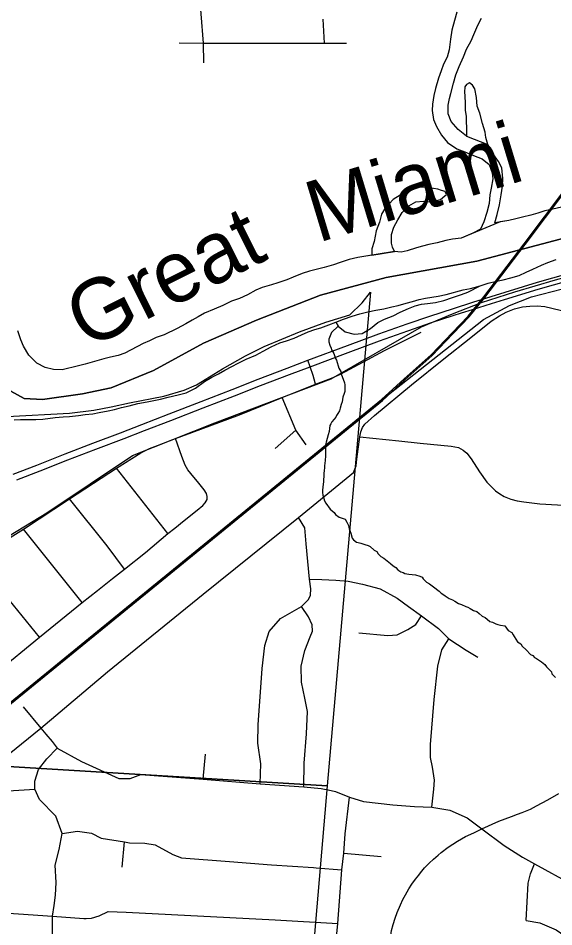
# Model space of a CAD drawing. Extents: x -7.3 to 34, y 0 to 22.
# Drawn here: x 2.852 to 3.68, y 15.96 to 17.363 of the extents above; entities that cross this region are included whole.
import ezdxf

# ---------------------------------------------------------------- set-up
doc = ezdxf.new("R2010")
doc.units = 0
for name, color, linetype in [('GM_X_City_Street', 7, 'Continuous'), ('GM_X_Corporation', 7, 'Continuous'), ('GM_X_County_Road', 7, 'Continuous'), ('GM_X_Major_River', 7, 'Continuous'), ('GM_X_Major_River_Text', 7, 'Continuous'), ('GM_X_Minor_River', 7, 'Continuous'), ('GM_X_Rail_Line', 7, 'Continuous'), ('GM_X_State_Route', 7, 'Continuous'), ('GM_X_Township_Road', 7, 'Continuous')]:
    doc.layers.add(name, color=color, linetype=linetype)

msp = doc.modelspace()

# ---------------------------------------------------------------- linework, layer by layer
at = {"layer": 'GM_X_City_Street'}
for p, q in [((3.2495, 16.6986), (3.2815, 16.7273)), ((3.084, 16.5678), (3.0044, 16.6683)), ((2.9513, 16.461), (2.8605, 16.5745)), ((3.1384, 16.1882), (3.1421, 16.227)), ((2.7616, 16.1658), (2.8784, 16.1728)), ((3.0134, 16.0522), (3.0169, 16.0912)), ((3.3559, 16.0738), (3.4137, 16.069)), ((3.313, 16.0513), (3.3525, 16.0483))]:
    msp.add_line(p, q, dxfattribs=at)
for points in [[(3.3806, 16.7168), (3.3818, 16.7247), (3.3844, 16.7311), (3.3881, 16.7366), (3.4032, 16.75), (3.4602, 16.7972), (3.5101, 16.8371), (3.5518, 16.8703), (3.5837, 16.8955), (3.5961, 16.9039), (3.6068, 16.9095), (3.6197, 16.9146), (3.6318, 16.9174), (3.643, 16.9187), (3.6546, 16.9189), (3.6665, 16.9179), (3.69, 16.9124), (3.7103, 16.9072), (3.7215, 16.9044), (3.7303, 16.9036), (3.7395, 16.9039), (3.7514, 16.904)], [(3.3121, 16.7984), (3.3369, 16.8077), (3.3504, 16.8138), (3.3864, 16.8327), (3.4188, 16.8503), (3.4752, 16.8784)], [(3.2976, 16.7043), (3.2815, 16.7273), (3.2607, 16.7777)], [(3.1447, 16.6201), (3.1446, 16.6246), (3.1434, 16.6296), (3.14, 16.6349), (3.1319, 16.6453), (3.1193, 16.6602), (3.1148, 16.6658), (3.1107, 16.6732), (3.1052, 16.6865), (3.0956, 16.7142)], [(3.3706, 16.6616), (3.3747, 16.6719), (3.3761, 16.6826), (3.3806, 16.7168)], [(2.451, 15.9102), (2.5692, 16.0102), (2.617, 16.0491), (2.6686, 16.0914), (2.7616, 16.1658), (2.8874, 16.2669), (2.9907, 16.354), (3.1385, 16.4741), (3.2859, 16.5922), (3.3706, 16.6616)], [(2.4737, 16.082), (2.5003, 16.0943), (2.5508, 16.1345), (2.6783, 16.2396), (2.685, 16.2457), (2.7515, 16.2992), (2.8184, 16.353), (2.8852, 16.4076), (2.9513, 16.461), (2.975, 16.4798), (2.9982, 16.4983), (3.0166, 16.5127), (3.0495, 16.5384), (3.084, 16.5678), (3.0945, 16.5756), (3.1088, 16.5876), (3.1289, 16.6036), (3.138, 16.611), (3.1414, 16.6147), (3.1447, 16.6201)], [(3.0166, 16.5127), (2.9898, 16.5486), (2.9319, 16.6213)], [(3.2267, 16.181), (3.2273, 16.2118), (3.2231, 16.2439), (3.2235, 16.272), (3.2297, 16.359), (3.2337, 16.3945), (3.2404, 16.4162), (3.2577, 16.4362), (3.2901, 16.4548), (3.3013, 16.4656), (3.3044, 16.4722), (3.3049, 16.4822), (3.3026, 16.4971), (3.2975, 16.5517), (3.2953, 16.5765), (3.2859, 16.5922)], [(2.8852, 16.4076), (2.8182, 16.4898), (2.8093, 16.5025), (2.801, 16.5158), (2.7927, 16.5321)], [(3.3026, 16.4971), (3.322, 16.4965), (3.3433, 16.4953), (3.3624, 16.494), (3.3847, 16.4894), (3.412, 16.4819), (3.4384, 16.4679), (3.4558, 16.4551), (3.4758, 16.4404), (3.5021, 16.4207), (3.5178, 16.405), (3.545, 16.3876), (3.5628, 16.3767)], [(3.2939, 16.1763), (3.2945, 16.2129), (3.2981, 16.2583), (3.2996, 16.2925), (3.2953, 16.3135), (3.2903, 16.3382), (3.2898, 16.3625), (3.2953, 16.3867), (3.3037, 16.4079), (3.3071, 16.4168), (3.3069, 16.4265), (3.3012, 16.4389), (3.2901, 16.4548)], [(3.379, 16.4141), (3.424, 16.41), (3.4381, 16.4113), (3.4548, 16.4192), (3.467, 16.4272), (3.4758, 16.4404)], [(3.4918, 16.145), (3.4947, 16.1728), (3.4961, 16.1866), (3.4929, 16.2065), (3.4897, 16.2217), (3.4895, 16.2415), (3.4956, 16.3112), (3.5008, 16.3629), (3.5072, 16.388), (3.5178, 16.405)], [(2.8601, 16.2999), (2.8874, 16.2669), (2.8954, 16.2578), (2.9049, 16.2462), (2.9129, 16.2363), (2.9503, 16.2156), (3.0083, 16.1891), (3.0256, 16.1891), (3.0421, 16.1952), (3.1384, 16.1882), (3.2267, 16.181), (3.2939, 16.1763), (3.3209, 16.1739), (3.3258, 16.1729)], [(2.8852, 15.856), (2.8914, 15.8756), (2.9053, 15.9451), (2.9054, 15.9766), (2.908, 15.9932), (2.91, 16.0092), (2.9111, 16.0286), (2.9096, 16.0553), (2.9158, 16.0798), (2.9204, 16.1043), (2.9105, 16.1312), (2.8852, 16.157), (2.8784, 16.1728), (2.878, 16.1851), (2.8839, 16.2031), (2.8969, 16.2196), (2.9129, 16.2363)], [(3.3258, 16.1729), (3.3317, 16.1717), (3.3428, 16.1694), (3.3647, 16.1606), (3.386, 16.1536), (3.4317, 16.1484), (3.4649, 16.146), (3.4918, 16.145), (3.5197, 16.1405), (3.5462, 16.1287), (3.5691, 16.1116), (3.6036, 16.086), (3.632, 16.0675), (3.6506, 16.0574), (3.7088, 16.0253), (3.7341, 16.0168), (3.7648, 16.013), (3.7864, 16.0151), (3.8265, 16.018), (3.8756, 16.0249), (3.9397, 16.0179), (3.9801, 16.0031), (3.9807, 16.0028), (4.0236, 15.9862)], [(3.3285, 15.7545), (3.3385, 15.882), (3.3464, 15.9652), (3.3525, 16.0483), (3.3559, 16.0738), (3.358, 16.1037), (3.3647, 16.1606)], [(2.9204, 16.1043), (2.9441, 16.1081), (2.9656, 16.1046), (2.9809, 16.0971), (3.0169, 16.0912), (3.0245, 16.0901), (3.0481, 16.0892), (3.0644, 16.0866), (3.0916, 16.0717), (3.105, 16.0665), (3.1793, 16.0611), (3.2438, 16.0559), (3.309, 16.0516), (3.313, 16.0513)], [(3.6375, 15.97), (3.6405, 16.0276), (3.6445, 16.0422), (3.6506, 16.0574)], [(2.5692, 16.0102), (2.5823, 16.0058), (2.6248, 16.0016), (2.7998, 15.9837), (2.9054, 15.9766), (2.9537, 15.9728), (2.9577, 15.973)], [(2.9577, 15.973), (2.9656, 15.9734), (2.9777, 15.977), (2.9914, 15.9837), (3.0195, 15.9828), (3.2499, 15.9709), (3.3464, 15.9652)], [(3.6375, 15.97), (3.6585, 15.9666), (3.684, 15.9555), (3.6971, 15.9464), (3.7075, 15.9375), (3.731, 15.9214), (3.7512, 15.9094), (3.7588, 15.9067), (3.8115, 15.8965), (3.8522, 15.8895), (3.8783, 15.8839), (3.9009, 15.8712), (3.9216, 15.8562), (3.9406, 15.8468), (3.9784, 15.8335), (4.0152, 15.8291), (4.0396, 15.8287), (4.0767, 15.8393), (4.1145, 15.8459), (4.1191, 15.8467), (4.1778, 15.8643), (4.1983, 15.8701)]]:
    msp.add_lwpolyline(points, dxfattribs=at)
at = {"layer": 'GM_X_Corporation'}
for points in [[(3.7543, 17.039), (3.5614, 16.9883), (3.4213, 16.9628), (3.3195, 16.9357), (3.2207, 16.8971), (3.1387, 16.8614), (3.0618, 16.8191), (2.996, 16.7927), (2.9517, 16.7835), (2.8903, 16.7745), (2.8615, 16.7762), (2.8411, 16.7875), (2.825, 16.807), (2.8151, 16.8289), (2.8045, 16.8509), (2.7965, 16.8622), (2.7873, 16.8705), (2.7646, 16.894), (2.72, 16.9194), (2.7253, 17.2786), (2.7319, 17.6124)], [(2.7319, 17.6124), (2.7253, 17.2786), (2.72, 16.9194), (2.7646, 16.894), (2.7873, 16.8705), (2.7965, 16.8622), (2.8045, 16.8509), (2.8151, 16.8289), (2.825, 16.807), (2.8411, 16.7875), (2.8615, 16.7762), (2.8903, 16.7745), (2.9517, 16.7835), (2.996, 16.7927), (3.0618, 16.8191), (3.1387, 16.8614), (3.2207, 16.8971), (3.3195, 16.9357), (3.4213, 16.9628), (3.5614, 16.9883), (3.7543, 17.039)], [(2.7319, 17.6124), (2.7253, 17.2786), (2.72, 16.9194), (2.7646, 16.894), (2.7873, 16.8705), (2.7965, 16.8622), (2.8045, 16.8509), (2.8151, 16.8289), (2.825, 16.807), (2.8411, 16.7875), (2.8615, 16.7762), (2.8903, 16.7745), (2.9517, 16.7835), (2.996, 16.7927), (3.0618, 16.8191), (3.1387, 16.8614), (3.2207, 16.8971), (3.3195, 16.9357), (3.4213, 16.9628), (3.5614, 16.9883), (3.7543, 17.039)], [(3.7543, 17.039), (3.5614, 16.9883), (3.4213, 16.9628), (3.3195, 16.9357), (3.2207, 16.8971), (3.1387, 16.8614), (3.0618, 16.8191), (2.996, 16.7927), (2.9517, 16.7835), (2.8903, 16.7745), (2.8615, 16.7762), (2.8411, 16.7875)], [(3.7543, 17.039), (3.5614, 16.9883), (3.4213, 16.9628), (3.3195, 16.9357), (3.2207, 16.8971), (3.1387, 16.8614), (3.0618, 16.8191), (2.996, 16.7927), (2.9517, 16.7835), (2.8903, 16.7745), (2.8615, 16.7762), (2.8411, 16.7875)], [(2.8353, 16.7484), (2.9316, 16.7533), (2.9692, 16.7582), (2.9962, 16.7633), (3.0243, 16.7692), (3.0776, 16.7799), (3.1092, 16.7887), (3.1279, 16.7971), (3.1682, 16.822), (3.2038, 16.8421), (3.2325, 16.8563), (3.2871, 16.8791), (3.3279, 16.8938), (3.3653, 16.9055), (3.3842, 16.9237), (3.397, 16.9401), (3.3302, 16.1779), (2.2589, 16.243)]]:
    msp.add_lwpolyline(points, dxfattribs=at)
msp.add_lwpolyline([(2.2589, 16.243), (3.3302, 16.1779), (3.2417, 15.1468), (2.2068, 15.2308)], close=True, dxfattribs=at)
at = {"layer": 'GM_X_County_Road'}
for points in [[(3.3806, 16.7168), (3.4407, 16.7108), (3.4738, 16.707), (3.5216, 16.7026), (3.5331, 16.7003), (3.5404, 16.6965), (3.5459, 16.6914), (3.5525, 16.6829), (3.5656, 16.6629), (3.577, 16.647), (3.5833, 16.6399), (3.5901, 16.6335), (3.5968, 16.6289), (3.6038, 16.6248), (3.614, 16.6206), (3.6237, 16.6179), (3.6342, 16.6163), (3.6585, 16.6136), (3.6858, 16.6117), (3.717, 16.6104), (3.773, 16.6064)], [(3.6241, 16.1339), (3.6314, 16.1366), (3.6445, 16.1421), (3.6537, 16.1471), (3.6713, 16.1565), (3.6882, 16.1659)], [(3.5691, 16.1116), (3.5952, 16.1231), (3.6151, 16.1304), (3.6241, 16.1339)], [(3.5014, 16.071), (3.5061, 16.0751), (3.5168, 16.083), (3.5317, 16.0923), (3.5438, 16.0996), (3.5565, 16.1053), (3.5691, 16.1116)], [(3.4262, 15.9355), (3.4269, 15.9402), (3.4282, 15.9472), (3.4297, 15.9546), (3.4319, 15.9636), (3.435, 15.9734), (3.4382, 15.9823), (3.4432, 15.994), (3.4471, 16.0023), (3.451, 16.0094), (3.4564, 16.0186), (3.4611, 16.026), (3.4664, 16.0336), (3.4715, 16.0401), (3.4743, 16.0437), (3.4807, 16.0511), (3.4877, 16.0586), (3.4943, 16.0648), (3.5014, 16.071)]]:
    msp.add_lwpolyline(points, dxfattribs=at)
at = {"layer": 'GM_X_Major_River'}
for p, q in [((3.5451, 17.181), (3.5785, 17.1681)), ((3.399, 16.9972), (3.434, 17.0028))]:
    msp.add_line(p, q, dxfattribs=at)
for points in [[(3.5304, 17.3725), (3.5267, 17.3597), (3.5229, 17.3446), (3.5206, 17.3309), (3.5187, 17.3147), (3.5153, 17.303), (3.5097, 17.2921), (3.5061, 17.2819), (3.5023, 17.2706), (3.4974, 17.2548), (3.4949, 17.2439)], [(3.5211, 17.2468), (3.5253, 17.2632), (3.529, 17.2757), (3.5339, 17.2888), (3.5407, 17.3035), (3.5456, 17.3155), (3.5524, 17.3286), (3.5568, 17.3384), (3.5629, 17.3527), (3.5685, 17.3636)], [(3.5785, 17.1681), (3.575, 17.1792), (3.5741, 17.1872), (3.5699, 17.2009), (3.5658, 17.2166), (3.5619, 17.2273), (3.5607, 17.2411), (3.5584, 17.254), (3.5544, 17.2598), (3.5499, 17.2634), (3.5453, 17.2608), (3.5429, 17.2571), (3.5424, 17.2491), (3.543, 17.2434), (3.5434, 17.2316), (3.5431, 17.2206), (3.5448, 17.2122), (3.545, 17.205), (3.5455, 17.1932), (3.5451, 17.181)], [(3.5451, 17.181), (3.5325, 17.1916), (3.5218, 17.2037), (3.5172, 17.2156), (3.5172, 17.2288), (3.5193, 17.2391), (3.5211, 17.2468)], [(3.4949, 17.2439), (3.493, 17.2306), (3.4923, 17.2207), (3.4946, 17.207), (3.4989, 17.1963), (3.5065, 17.1828), (3.5161, 17.1715), (3.5306, 17.1617), (3.5426, 17.1568), (3.5561, 17.1511), (3.5696, 17.1462), (3.5804, 17.1372), (3.585, 17.1246), (3.5859, 17.1151), (3.5836, 17.1007), (3.5815, 17.0905), (3.5803, 17.0772), (3.5766, 17.0633), (3.572, 17.049), (3.5668, 17.0377), (3.5552, 17.0313)], [(3.589, 17.0474), (3.5928, 17.0602), (3.5966, 17.0749), (3.5989, 17.0904), (3.6008, 17.1037), (3.6015, 17.1158), (3.6, 17.1322), (3.5949, 17.1418), (3.5847, 17.1565), (3.5785, 17.1681)], [(3.434, 17.0028), (3.4311, 17.0096), (3.4297, 17.0161), (3.4297, 17.0294), (3.433, 17.0407), (3.439, 17.0519), (3.4457, 17.0631), (3.4562, 17.0735), (3.467, 17.0797), (3.4788, 17.0809), (3.4924, 17.0798), (3.505, 17.0833), (3.512, 17.0892), (3.5147, 17.091), (3.5122, 17.0957), (3.5069, 17.0973), (3.5013, 17.0993), (3.4941, 17.1003), (3.4809, 17.1018), (3.4684, 17.1025), (3.455, 17.0975), (3.443, 17.0902), (3.4319, 17.0832), (3.426, 17.0765), (3.4202, 17.071), (3.4142, 17.0609), (3.4108, 17.0484), (3.4059, 17.0349), (3.4029, 17.0186), (3.3992, 17.0073), (3.399, 16.9972)], [(3.6924, 17.0716), (3.679, 17.0685), (3.6664, 17.0657), (3.6557, 17.0621), (3.645, 17.0593), (3.6317, 17.0561), (3.6214, 17.0537), (3.6107, 17.0509), (3.589, 17.0474)], [(3.6924, 17.0716), (3.679, 17.0685), (3.6664, 17.0657), (3.6557, 17.0621), (3.645, 17.0593), (3.6317, 17.0561), (3.6214, 17.0537), (3.6107, 17.0509), (3.5974, 17.0489)], [(3.5974, 17.0489), (3.5372, 17.0239), (3.5235, 17.0219), (3.5133, 17.0198), (3.4999, 17.0163), (3.4873, 17.0139), (3.4774, 17.0114), (3.4679, 17.0086), (3.4537, 17.0043), (3.4442, 17.0022), (3.434, 17.0028)], [(3.5552, 17.0313), (3.5372, 17.0239), (3.5235, 17.0219), (3.5133, 17.0198), (3.4999, 17.0163), (3.4873, 17.0139), (3.4774, 17.0114), (3.4679, 17.0086), (3.4537, 17.0043), (3.4442, 17.0022), (3.434, 17.0028)], [(3.434, 17.0028), (3.3776, 16.9937), (3.3642, 16.9906), (3.3501, 16.9863), (3.3398, 16.9824)], [(3.399, 16.9972), (3.3776, 16.9937), (3.3642, 16.9906), (3.3501, 16.9863), (3.3398, 16.9824)], [(2.8462, 16.743), (2.856, 16.7435), (2.8663, 16.7437), (2.8799, 16.7434), (2.8906, 16.744), (2.9096, 16.7466), (2.9222, 16.7475), (2.932, 16.7484), (2.9457, 16.7497), (2.956, 16.7514), (2.9678, 16.7526), (2.9777, 16.7543), (2.9914, 16.7571), (3.0013, 16.7592), (3.0124, 16.762), (3.0239, 16.7648), (3.0376, 16.7683), (3.0517, 16.771), (3.0723, 16.7752), (3.0845, 16.778), (3.0997, 16.7818), (3.1119, 16.7846), (3.1265, 16.7919), (3.1404, 16.8023), (3.1516, 16.8089), (3.1619, 16.8143), (3.1719, 16.8198), (3.1827, 16.8253), (3.1923, 16.8308), (3.2049, 16.837), (3.2199, 16.8432), (3.231, 16.849), (3.2437, 16.8556), (3.2567, 16.8621), (3.2674, 16.865), (3.2792, 16.8693), (3.2904, 16.8744), (3.3007, 16.8791), (3.3107, 16.8827), (3.3202, 16.8852), (3.3328, 16.8898), (3.3435, 16.8938), (3.3554, 16.8985), (3.3688, 16.9031), (3.3806, 16.9067), (3.3928, 16.9099), (3.405, 16.9123), (3.4176, 16.9143), (3.4298, 16.9175), (3.4397, 16.9199), (3.4519, 16.9235), (3.4619, 16.9259), (3.4722, 16.9288), (3.4821, 16.9308), (3.4916, 16.9325), (3.5015, 16.9339), (3.5141, 16.9366), (3.54, 16.9437), (3.5515, 16.9461), (3.5664, 16.95), (3.579, 16.9539), (3.5919, 16.9571), (3.6022, 16.9595), (3.6137, 16.9623), (3.6267, 16.9662), (3.6378, 16.9709), (3.6477, 16.9757), (3.6612, 16.9819), (3.6711, 16.9862), (3.6841, 16.9909)], [(3.3398, 16.9824), (3.3256, 16.9781), (3.3131, 16.9753), (3.3028, 16.9729), (3.2913, 16.9693), (3.2775, 16.9635), (3.2676, 16.9595), (3.2538, 16.9549), (3.2439, 16.9517), (3.2297, 16.9474), (3.2198, 16.9434), (3.2067, 16.9361), (3.1945, 16.9306), (3.1822, 16.9263), (3.1688, 16.9198), (3.1554, 16.914), (3.1404, 16.9078), (3.1308, 16.9023), (3.1212, 16.8972), (3.1116, 16.8913), (3.0982, 16.884), (3.0782, 16.8745), (3.0656, 16.8702), (3.0553, 16.8651), (3.0457, 16.8608), (3.0173, 16.8462), (3.007, 16.8426), (2.9951, 16.8398), (2.9848, 16.8373), (2.9703, 16.8331), (2.9562, 16.8292), (2.9455, 16.8264), (2.9203, 16.8201), (2.9071, 16.8207), (2.8942, 16.824), (2.8811, 16.8307), (2.8688, 16.8428), (2.8608, 16.857), (2.8565, 16.8669), (2.8522, 16.8803)], [(3.3398, 16.9824), (3.3256, 16.9781), (3.3131, 16.9753), (3.3028, 16.9729), (3.2913, 16.9693), (3.2775, 16.9635), (3.2676, 16.9595), (3.2538, 16.9549), (3.2439, 16.9517), (3.2297, 16.9474), (3.2198, 16.9434), (3.2067, 16.9361), (3.1945, 16.9306), (3.1822, 16.9263), (3.1688, 16.9198), (3.1554, 16.914), (3.1404, 16.9078), (3.1308, 16.9023), (3.1212, 16.8972), (3.1116, 16.8913), (3.0982, 16.884), (3.0782, 16.8745), (3.0656, 16.8702), (3.0553, 16.8651), (3.0457, 16.8608), (3.0173, 16.8462), (3.007, 16.8426), (2.9951, 16.8398), (2.9848, 16.8373), (2.9703, 16.8331), (2.9562, 16.8292), (2.9455, 16.8264), (2.9203, 16.8201), (2.9071, 16.8207), (2.8942, 16.824), (2.8811, 16.8307), (2.8688, 16.8428), (2.8608, 16.857), (2.8565, 16.8669), (2.8522, 16.8803)]]:
    msp.add_lwpolyline(points, dxfattribs=at)
at = {"layer": 'GM_X_Minor_River'}
for points in [[(3.3435, 16.8938), (3.3468, 16.888), (3.3576, 16.8791), (3.3716, 16.8754), (3.3841, 16.8762), (3.3968, 16.8843), (3.4084, 16.8932), (3.4188, 16.8987), (3.4318, 16.9038), (3.4429, 16.9092), (3.4556, 16.915), (3.4659, 16.9194), (3.4758, 16.9215), (3.4853, 16.9228), (3.4975, 16.9244), (3.5105, 16.9272), (3.5235, 16.9319), (3.5376, 16.9365), (3.5476, 16.9405), (3.5664, 16.95)], [(3.3468, 16.888), (3.3369, 16.8779), (3.3346, 16.8726), (3.3327, 16.8677), (3.3327, 16.8636), (3.3341, 16.8586), (3.3364, 16.8537), (3.3367, 16.851), (3.339, 16.8483), (3.3401, 16.8453), (3.3412, 16.8426), (3.3431, 16.8377), (3.3442, 16.835), (3.3479, 16.8228), (3.3509, 16.8175), (3.3516, 16.8141), (3.3568, 16.8004), (3.3571, 16.797), (3.3575, 16.7928), (3.3571, 16.7867), (3.3563, 16.7837), (3.3544, 16.778), (3.3532, 16.7708), (3.3516, 16.767), (3.3501, 16.761), (3.3489, 16.7568), (3.3466, 16.7527), (3.3447, 16.7497), (3.3432, 16.747), (3.3409, 16.744), (3.3374, 16.7399), (3.3355, 16.7368), (3.334, 16.7342), (3.3332, 16.7251), (3.3316, 16.7198), (3.3285, 16.7085), (3.3273, 16.7047), (3.3272, 16.688), (3.3268, 16.68), (3.3264, 16.6766), (3.326, 16.6717), (3.3259, 16.6683), (3.3255, 16.6656), (3.3251, 16.6596), (3.3247, 16.6558), (3.3243, 16.6512), (3.3243, 16.6478), (3.3231, 16.6391), (3.3227, 16.6345), (3.3226, 16.6311), (3.3234, 16.6266), (3.3241, 16.6239), (3.326, 16.6178), (3.3282, 16.6144), (3.3346, 16.6049), (3.3406, 16.5999), (3.3428, 16.5968), (3.3485, 16.593), (3.3519, 16.5918), (3.3579, 16.5895), (3.3605, 16.5853), (3.3631, 16.5799), (3.3638, 16.575), (3.3668, 16.5681), (3.3686, 16.5605), (3.3709, 16.5579), (3.3754, 16.5544), (3.378, 16.5536), (3.3818, 16.5525), (3.3882, 16.5505), (3.3935, 16.5489), (3.3965, 16.5474), (3.4029, 16.542), (3.4067, 16.5397), (3.4089, 16.5363), (3.4131, 16.5321), (3.4176, 16.5294), (3.4251, 16.5232), (3.4277, 16.5213), (3.4319, 16.5175), (3.436, 16.5152), (3.4394, 16.5117), (3.4439, 16.5086), (3.4477, 16.5075), (3.4503, 16.5059), (3.4563, 16.5047), (3.4666, 16.5035), (3.473, 16.5019), (3.4767, 16.5004), (3.4786, 16.4977), (3.4835, 16.4924), (3.4884, 16.49), (3.4944, 16.485), (3.503, 16.4785), (3.5061, 16.4755), (3.5087, 16.4739), (3.5124, 16.4712), (3.5188, 16.467), (3.5237, 16.4651), (3.5275, 16.4631), (3.5328, 16.4597)], [(3.5328, 16.4597), (3.5377, 16.4581), (3.5445, 16.4546), (3.5475, 16.4538), (3.5509, 16.4515), (3.5562, 16.4488), (3.5614, 16.4469), (3.5648, 16.4438), (3.5697, 16.44), (3.5742, 16.438), (3.5772, 16.4354), (3.5814, 16.4315), (3.5855, 16.4304), (3.5908, 16.428), (3.5938, 16.4269), (3.598, 16.4261), (3.6044, 16.4249), (3.6074, 16.4214), (3.61, 16.418), (3.6153, 16.4145), (3.6175, 16.4111), (3.619, 16.4084), (3.6242, 16.4004), (3.6291, 16.397), (3.6314, 16.3935), (3.6374, 16.3878), (3.6445, 16.3805), (3.6479, 16.379), (3.6505, 16.3763), (3.6536, 16.3744), (3.6611, 16.3694), (3.6637, 16.3671), (3.6663, 16.3651), (3.669, 16.3617), (3.6716, 16.359), (3.6765, 16.3537), (3.6772, 16.351), (3.6828, 16.3453)]]:
    msp.add_lwpolyline(points, dxfattribs=at)
at = {"layer": 'GM_X_Rail_Line'}
for points in [[(3.6345, 17.0151), (3.985, 17.4802), (4.3732, 17.9988), (4.5251, 18.2021), (4.7981, 18.5667), (5.0774, 18.9371), (5.1565, 19.0428), (5.1846, 19.0805), (5.2002, 19.101), (5.5499, 19.5711), (5.7863, 19.8846), (5.8776, 20.0139)], [(3.636, 17.0139), (3.9865, 17.479), (4.3757, 17.998), (4.5264, 18.1998), (4.796, 18.5597), (5.0789, 18.9359), (5.158, 19.0417), (5.1862, 19.0793), (5.2017, 19.0998), (5.5529, 19.5699), (5.7879, 19.8835), (5.8792, 20.0128)], [(3.5684, 16.9242), (3.6203, 16.9407), (3.683, 16.9592), (3.9788, 17.0405), (4.0548, 17.0607), (4.1528, 17.0906), (4.2816, 17.1367), (4.4251, 17.1935), (4.4536, 17.2072)], [(3.415, 16.7747), (3.5714, 16.898), (3.6117, 16.9195), (3.6457, 16.9333), (3.7099, 16.9497), (3.823, 16.9805), (3.8987, 17.0026), (4.0866, 17.0531), (4.2789, 17.1213), (4.4523, 17.1912)], [(2.1, 15.707), (2.1249, 15.7268), (2.5382, 16.0605), (2.9557, 16.4006), (3.414, 16.7747), (3.4488, 16.8065), (3.4909, 16.8436), (3.5233, 16.8776), (3.548, 16.9034), (3.5722, 16.9333), (3.6345, 17.0151)], [(2.1, 15.7046), (2.1261, 15.7254), (2.5394, 16.059), (2.9569, 16.3991), (3.4153, 16.7732), (3.4501, 16.805), (3.4922, 16.8422), (3.5247, 16.8762), (3.5495, 16.9022), (3.5737, 16.9321), (3.636, 17.0139)], [(2.1, 15.9624), (2.1372, 15.9999), (2.2187, 16.0756), (2.3348, 16.1655), (2.4005, 16.2159), (2.4362, 16.2448), (2.4901, 16.3128), (2.5242, 16.3462), (2.5948, 16.4062), (2.7068, 16.4842), (2.8968, 16.5994), (3.0293, 16.6878), (3.1562, 16.7383), (3.3361, 16.8064), (3.4758, 16.8869), (3.5239, 16.9069), (3.5684, 16.9242)]]:
    msp.add_lwpolyline(points, dxfattribs=at)
at = {"layer": 'GM_X_State_Route'}
for points in [[(2.8449, 16.6594), (2.8811, 16.6733), (2.9252, 16.6906), (2.9681, 16.7069), (3.0106, 16.7232), (3.0434, 16.7358), (3.0856, 16.7524), (3.1355, 16.7715), (3.1832, 16.7902), (3.2235, 16.8057), (3.2683, 16.8231), (3.3002, 16.835), (3.3616, 16.8579), (3.4101, 16.876), (3.4538, 16.8914), (3.4888, 16.9031), (3.5253, 16.915), (3.5549, 16.9246), (3.5833, 16.9337), (3.6553, 16.9555), (3.7025, 16.969)], [(3.6041, 16.929), (3.6562, 16.9447), (3.7034, 16.9583), (3.7179, 16.9623)], [(3.5375, 16.9083), (3.5547, 16.9137), (3.5842, 16.923), (3.6041, 16.929)], [(2.8502, 16.6506), (2.8863, 16.6645), (2.9293, 16.6811), (2.9726, 16.6978), (3.0161, 16.7145), (3.0475, 16.7267), (3.0882, 16.7423), (3.1383, 16.7617), (3.1869, 16.7804), (3.2272, 16.7959), (3.272, 16.8132), (3.3039, 16.8252), (3.3625, 16.8472), (3.411, 16.8652), (3.4547, 16.8806), (3.4913, 16.8932), (3.525, 16.9043), (3.5375, 16.9083)]]:
    msp.add_lwpolyline(points, dxfattribs=at)
at = {"layer": 'GM_X_Township_Road'}
msp.add_line((3.3235, 17.3619), (3.3254, 17.3247), dxfattribs=at)
for points in [[(3.0575, 17.5069), (3.0627, 17.4938), (3.0713, 17.4831), (3.0786, 17.4786), (3.0908, 17.4737), (3.1009, 17.4673), (3.108, 17.4615), (3.1132, 17.4566), (3.1176, 17.4509), (3.1239, 17.4418), (3.1287, 17.4286), (3.1314, 17.4159), (3.1385, 17.325), (3.1387, 17.2946)], [(3.1011, 17.3251), (3.1385, 17.325), (3.3254, 17.3247), (3.3599, 17.3246)], [(3.3101, 16.806), (3.3085, 16.8116), (3.3039, 16.8252), (3.3002, 16.835)], [(2.5622, 16.3763), (2.5724, 16.3846), (2.604, 16.41), (2.6279, 16.4286), (2.6401, 16.4369), (2.7126, 16.4854), (2.755, 16.5113), (2.7927, 16.5321), (2.8605, 16.5745), (2.9319, 16.6213), (3.0044, 16.6683), (3.0421, 16.6919), (3.0556, 16.6987), (3.0677, 16.7035), (3.0956, 16.7142), (3.1211, 16.7236), (3.1946, 16.7506), (3.2607, 16.7777), (3.3121, 16.7984), (3.3101, 16.806)]]:
    msp.add_lwpolyline(points, dxfattribs=at)

# ---------------------------------------------------------------- texts
at = {"layer": 'GM_X_Major_River_Text'}
for s, rotation, p in [('Miami', 16.869, (3.3153, 17.0162)), ('Great', 26.554, (2.9579, 16.8509))]:
    msp.add_text(s, height=0.0947, rotation=rotation, dxfattribs=at).set_placement(p)

doc.saveas('drawing.dxf')
